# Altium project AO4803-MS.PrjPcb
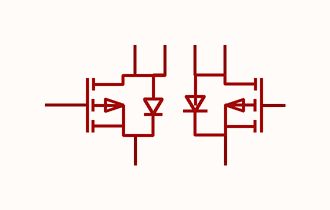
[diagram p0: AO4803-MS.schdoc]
1 sheet, 1 parts. Net scope: global (net labels, ports and power ports of the same name join across sheets).

## Sheet AO4803-MS.schdoc
size 127 x 101 mm

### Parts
Q?  ao4803-ms  [SOP-8_L4.9-W3.9-P1.27-LS6.0-BL]  (value not drawn)

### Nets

Not connected (* = marked no-connect by the designer): Q? 1(S1) 2(G1) 3(S2) 4(G2) 5(D2) 6(D2) 7(D1) 8(D1)

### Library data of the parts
Q? = ao4803-ms: 数量:2个P沟道;漏源电压(Vdss):30V;连续漏极电流(Id):5A;导通电阻(RDS(on)):52mΩ@10V;耗散功率(Pd):2W;阈值电压(Vgs(th)):2.4V;; Manufacturer: MSKSEMI(美森科); AddInBom: yes; ModelId: 75c24a7891ee4dd6bdac16a7163ff87e; ModelName: SOP-8_L4.9-W3.9-P1.27-LS6.0-BL-1; ModelTransform: 192.913,236.22,0,0,0,0,-0.393,2.749,0; Number: 2个P沟道; Drain to Source Voltage: 30V; Current - Continuous Drain(Id): 5A; Pd - Power Dissipation: 2W; Gate Threshold Voltage (Vgs(th)): 2.4V; Gate Charge(Qg): 11nC@10V; Input Capacitance(Ciss): 520pF; Reverse Transfer Capacitance (Crss@Vds): 65pF; Output Capacitance(Coss): 100pF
